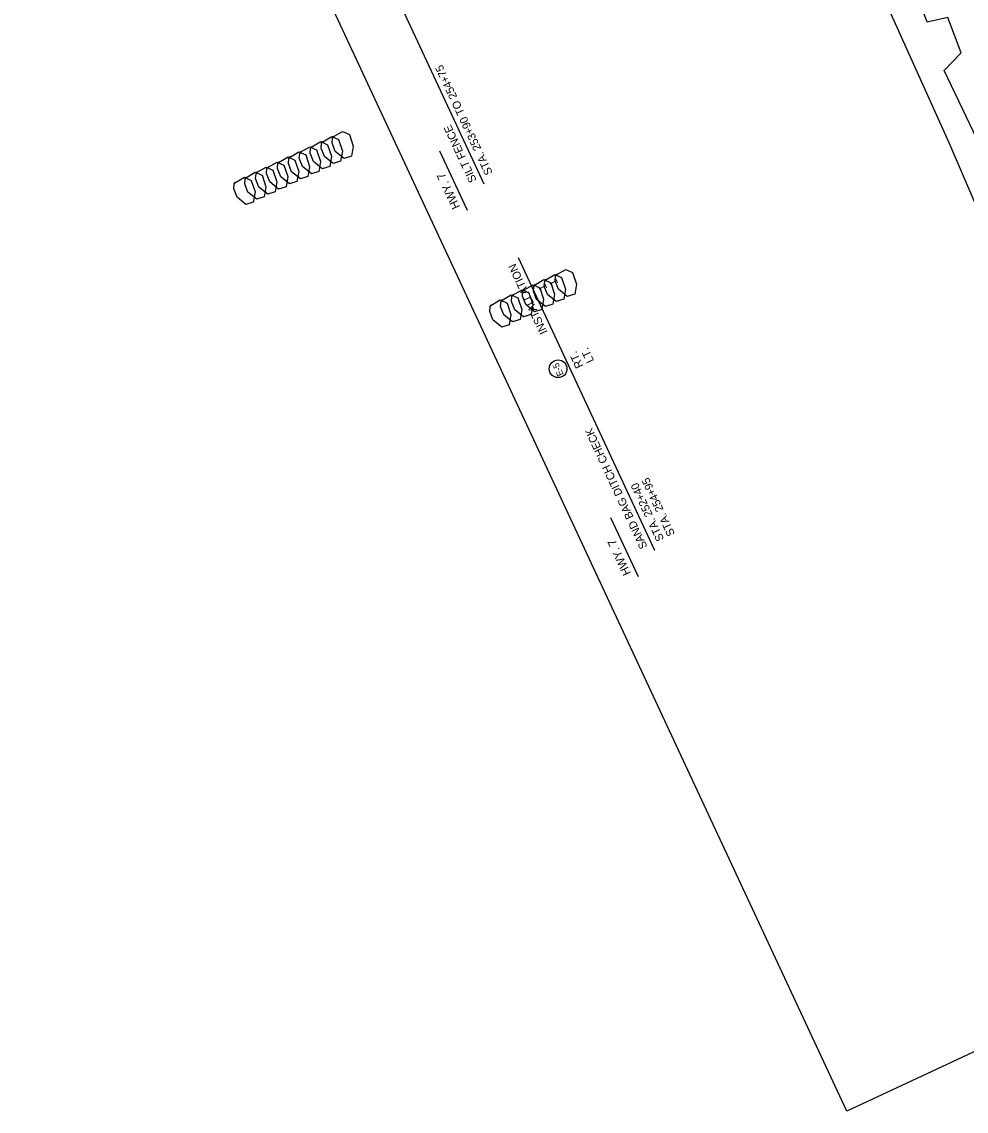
# Model space of a CAD drawing. Extents: x 964229 to 965790, y 1899262 to 1901428.
# Drawn here: x 964229 to 964934, y 1899262 to 1900076 of the extents above; entities that cross this region are included whole.
import ezdxf

# ---------------------------------------------------------------- set-up
doc = ezdxf.new("R2010")
doc.units = 0
for name, color, linetype in [('1', 7, 'Continuous'), ('44', 7, 'Continuous'), ('NO PLOT', 7, 'Continuous'), ('S_TREE', 7, 'Continuous')]:
    doc.layers.add(name, color=color, linetype=linetype)

msp = doc.modelspace()

# ---------------------------------------------------------------- linework, layer by layer
at = {"layer": '1'}
msp.add_circle((964629.55, 1899816.5), 6.61, dxfattribs=at)
at = {"layer": '44'}
for p, q in [((964574.3, 1899954.45), (964475.92, 1900165.44)), ((964561.91, 1899934.67), (964541.26, 1899978.94)), ((964701.88, 1899680.86), (964600.03, 1899899.28)), ((964689.48, 1899661.08), (964668.84, 1899705.35))]:
    msp.add_line(p, q, dxfattribs=at)
at = {"layer": 'NO PLOT'}
msp.add_lwpolyline([(964845.11, 1899262.24), (964344.7, 1900335.36), (964389.48, 1900356.24), (964306.73, 1900533.69), (964319.96, 1900539.86), (964228.89, 1900735.17), (964643.21, 1900928.38), (964770.42, 1900655.58), (964700.63, 1900623.04), (964880.25, 1900237.86), (964950.03, 1900270.4), (965070.98, 1900011.03), (965017.24, 1899985.98), (965162.05, 1899675.42), (965215.79, 1899700.48), (965317.44, 1899482.49)], close=True, dxfattribs=at)
msp.add_lwpolyline([(964845.11, 1899262.24), (964344.7, 1900335.36), (964389.48, 1900356.24), (964306.73, 1900533.69), (964319.96, 1900539.86), (964228.89, 1900735.17), (964643.21, 1900928.38), (964770.42, 1900655.58), (964700.63, 1900623.04), (964880.25, 1900237.86), (964950.03, 1900270.4), (965070.98, 1900011.03), (965017.24, 1899985.98), (965162.05, 1899675.42), (965215.79, 1899700.48), (965317.44, 1899482.49)], close=True, dxfattribs=at)
msp.add_lwpolyline([(964845.11, 1899262.24), (964344.7, 1900335.36), (964389.48, 1900356.24), (964306.73, 1900533.69), (964319.96, 1900539.86), (964228.89, 1900735.17), (964643.21, 1900928.38), (964770.42, 1900655.58), (964700.63, 1900623.04), (964880.25, 1900237.86), (964950.03, 1900270.4), (965070.98, 1900011.03), (965017.24, 1899985.98), (965162.05, 1899675.42), (965215.79, 1899700.48), (965317.44, 1899482.49)], close=True, dxfattribs=at)
msp.add_lwpolyline([(964743.2, 1900380.79), (964921.35, 1899985.44), (965071.82, 1899636.13), (965164.72, 1899429.12), (965178.4, 1899407.57), (965188.68, 1899415.47), (965049.43, 1899737.41), (965066.12, 1899749.34), (965054.6, 1899772.93), (965036.81, 1899766.7), (965016.41, 1899833.74), (964918.01, 1900039.22), (964930.54, 1900052.3), (964920.78, 1900078.79), (964905.36, 1900075.22), (964854.38, 1900212.3)], dxfattribs=at)
at = {"layer": 'S_TREE'}
for points in [[(964453.28, 1899985.76), (964460.42, 1899989.88), (964465.47, 1899987.58), (964468.38, 1899978.97), (964467.09, 1899971.45), (964461.52, 1899969.69), (964454.95, 1899975.02), (964452.54, 1899981.28), (964452.83, 1899984.97), (964453.91, 1899986.29)], [(964453.28, 1899985.76), (964460.42, 1899989.88), (964465.47, 1899987.58), (964468.38, 1899978.97), (964467.09, 1899971.45), (964461.52, 1899969.69), (964454.95, 1899975.02), (964452.54, 1899981.28), (964452.83, 1899984.97), (964453.91, 1899986.29)], [(964461.43, 1899989.56), (964468.57, 1899993.69), (964473.62, 1899991.38), (964476.53, 1899982.78), (964475.25, 1899975.25), (964469.68, 1899973.49), (964463.11, 1899978.82), (964460.7, 1899985.08), (964460.99, 1899988.78), (964462.07, 1899990.1)], [(964436.96, 1899978.15), (964444.1, 1899982.28), (964449.15, 1899979.97), (964452.06, 1899971.37), (964450.78, 1899963.84), (964445.21, 1899962.08), (964438.64, 1899967.41), (964436.23, 1899973.67), (964436.52, 1899977.36), (964437.6, 1899978.69)], [(964445.12, 1899981.96), (964452.26, 1899986.08), (964457.31, 1899983.78), (964460.22, 1899975.17), (964458.94, 1899967.65), (964453.36, 1899965.88), (964446.79, 1899971.22), (964444.38, 1899977.47), (964444.67, 1899981.17), (964445.76, 1899982.49)], [(964420.65, 1899970.54), (964427.79, 1899974.67), (964432.84, 1899972.37), (964435.75, 1899963.76), (964434.46, 1899956.24), (964428.89, 1899954.47), (964422.32, 1899959.8), (964419.91, 1899966.06), (964420.2, 1899969.76), (964421.29, 1899971.08)], [(964420.65, 1899970.54), (964427.79, 1899974.67), (964432.84, 1899972.37), (964435.75, 1899963.76), (964434.46, 1899956.24), (964428.89, 1899954.47), (964422.32, 1899959.8), (964419.91, 1899966.06), (964420.2, 1899969.76), (964421.29, 1899971.08)], [(964428.81, 1899974.35), (964435.95, 1899978.47), (964441, 1899976.17), (964443.91, 1899967.56), (964442.62, 1899960.04), (964437.05, 1899958.28), (964430.48, 1899963.61), (964428.07, 1899969.87), (964428.36, 1899973.56), (964429.44, 1899974.88)], [(964428.81, 1899974.35), (964435.95, 1899978.47), (964441, 1899976.17), (964443.91, 1899967.56), (964442.62, 1899960.04), (964437.05, 1899958.28), (964430.48, 1899963.61), (964428.07, 1899969.87), (964428.36, 1899973.56), (964429.44, 1899974.88)], [(964396.18, 1899959.13), (964403.32, 1899963.26), (964408.37, 1899960.96), (964411.28, 1899952.35), (964409.99, 1899944.83), (964404.42, 1899943.06), (964397.85, 1899948.39), (964395.44, 1899954.65), (964395.73, 1899958.35), (964396.82, 1899959.67)], [(964404.33, 1899962.94), (964411.48, 1899967.06), (964416.53, 1899964.76), (964419.44, 1899956.15), (964418.15, 1899948.63), (964412.58, 1899946.86), (964406.01, 1899952.2), (964403.6, 1899958.46), (964403.89, 1899962.15), (964404.97, 1899963.47)], [(964404.33, 1899962.94), (964411.48, 1899967.06), (964416.53, 1899964.76), (964419.44, 1899956.15), (964418.15, 1899948.63), (964412.58, 1899946.86), (964406.01, 1899952.2), (964403.6, 1899958.46), (964403.89, 1899962.15), (964404.97, 1899963.47)], [(964412.49, 1899966.74), (964419.63, 1899970.87), (964424.68, 1899968.56), (964427.59, 1899959.96), (964426.31, 1899952.43), (964420.74, 1899950.67), (964414.17, 1899956), (964411.76, 1899962.26), (964412.05, 1899965.95), (964413.13, 1899967.27)], [(964412.49, 1899966.74), (964419.63, 1899970.87), (964424.68, 1899968.56), (964427.59, 1899959.96), (964426.31, 1899952.43), (964420.74, 1899950.67), (964414.17, 1899956), (964411.76, 1899962.26), (964412.05, 1899965.95), (964413.13, 1899967.27)], [(964388.02, 1899955.33), (964395.16, 1899959.45), (964400.21, 1899957.15), (964403.12, 1899948.55), (964401.84, 1899941.02), (964396.27, 1899939.26), (964389.7, 1899944.59), (964387.29, 1899950.85), (964387.58, 1899954.54), (964388.66, 1899955.86)], [(964628.12, 1899886.57), (964635.26, 1899890.69), (964640.31, 1899888.39), (964643.22, 1899879.78), (964641.93, 1899872.26), (964636.36, 1899870.49), (964629.79, 1899875.83), (964627.38, 1899882.09), (964627.67, 1899885.78), (964628.75, 1899887.1)], [(964628.12, 1899886.57), (964635.26, 1899890.69), (964640.31, 1899888.39), (964643.22, 1899879.78), (964641.93, 1899872.26), (964636.36, 1899870.49), (964629.79, 1899875.83), (964627.38, 1899882.09), (964627.67, 1899885.78), (964628.75, 1899887.1)], [(964611.8, 1899878.96), (964618.94, 1899883.08), (964623.99, 1899880.78), (964626.9, 1899872.17), (964625.62, 1899864.65), (964620.05, 1899862.89), (964613.48, 1899868.22), (964611.07, 1899874.48), (964611.36, 1899878.17), (964612.44, 1899879.49)], [(964619.96, 1899882.76), (964627.1, 1899886.89), (964632.15, 1899884.59), (964635.06, 1899875.98), (964633.78, 1899868.46), (964628.2, 1899866.69), (964621.64, 1899872.02), (964619.22, 1899878.28), (964619.52, 1899881.98), (964620.6, 1899883.3)], [(964595.49, 1899871.35), (964602.63, 1899875.48), (964607.68, 1899873.17), (964610.59, 1899864.57), (964609.31, 1899857.05), (964603.73, 1899855.28), (964597.17, 1899860.61), (964594.75, 1899866.87), (964595.04, 1899870.57), (964596.13, 1899871.89)], [(964595.49, 1899871.35), (964602.63, 1899875.48), (964607.68, 1899873.17), (964610.59, 1899864.57), (964609.31, 1899857.05), (964603.73, 1899855.28), (964597.17, 1899860.61), (964594.75, 1899866.87), (964595.04, 1899870.57), (964596.13, 1899871.89)], [(964603.65, 1899875.16), (964610.79, 1899879.28), (964615.84, 1899876.98), (964618.75, 1899868.37), (964617.46, 1899860.85), (964611.89, 1899859.08), (964605.32, 1899864.42), (964602.91, 1899870.68), (964603.2, 1899874.37), (964604.28, 1899875.69)], [(964603.65, 1899875.16), (964610.79, 1899879.28), (964615.84, 1899876.98), (964618.75, 1899868.37), (964617.46, 1899860.85), (964611.89, 1899859.08), (964605.32, 1899864.42), (964602.91, 1899870.68), (964603.2, 1899874.37), (964604.28, 1899875.69)], [(964579.18, 1899863.75), (964586.32, 1899867.87), (964591.37, 1899865.57), (964594.28, 1899856.96), (964592.99, 1899849.44), (964587.42, 1899847.67), (964580.85, 1899853.01), (964578.44, 1899859.26), (964578.73, 1899862.96), (964579.81, 1899864.28)], [(964587.33, 1899867.55), (964594.47, 1899871.67), (964599.52, 1899869.37), (964602.43, 1899860.76), (964601.15, 1899853.24), (964595.58, 1899851.48), (964589.01, 1899856.81), (964586.6, 1899863.07), (964586.89, 1899866.76), (964587.97, 1899868.08)], [(964587.33, 1899867.55), (964594.47, 1899871.67), (964599.52, 1899869.37), (964602.43, 1899860.76), (964601.15, 1899853.24), (964595.58, 1899851.48), (964589.01, 1899856.81), (964586.6, 1899863.07), (964586.89, 1899866.76), (964587.97, 1899868.08)]]:
    msp.add_lwpolyline(points, dxfattribs=at)

# ---------------------------------------------------------------- texts
at = {"layer": '1'}
msp.add_text('E-5 ', height=4.8, rotation=115, dxfattribs=at).set_placement((964633.77, 1899812.4))
at = {"layer": '44'}
for s, height, rotation, p in [('STA. 253+90 TO 254+75', 6, 114.99998, (964580.8, 1899962.77)), ('SILT FENCE      ', 6, 114.99998, (964568.87, 1899957.21)), ('HWY. 7', 6.25, 115, (964556.43, 1899937.47)), ('INSTALLATION', 6, 115, (964621.71, 1899843.9)), ('1', 6, 115, (964629.79, 1899880.27)), ('1', 6, 115, (964621.63, 1899876.47)), ('RT.', 6, 115, (964648.46, 1899818.54)), ('LT.', 6, 115, (964656.55, 1899822.47)), ('SAND BAG DITCH CHECK', 6, 115, (964696.45, 1899683.61)), ('STA. 252+40', 6, 115, (964708.84, 1899689.39)), ('STA. 254+95', 6, 115, (964717, 1899693.2)), ('HWY. 7', 6.25, 115, (964684.01, 1899663.87))]:
    msp.add_text(s, height=height, rotation=rotation, dxfattribs=at).set_placement(p)

doc.saveas('drawing.dxf')
